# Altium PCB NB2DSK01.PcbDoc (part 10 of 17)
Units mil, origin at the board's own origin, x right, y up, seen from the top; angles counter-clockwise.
Board outline 11815 x 6500.03 mil, 8 copper layers (Top Layer, MidLayer1, MidLayer2, GND, PWR, MidLayer3, MidLayer4, Bottom Layer), stack 74.62 mil thick; 798 components, 1002 nets, 3927 pads, 3182 vias.
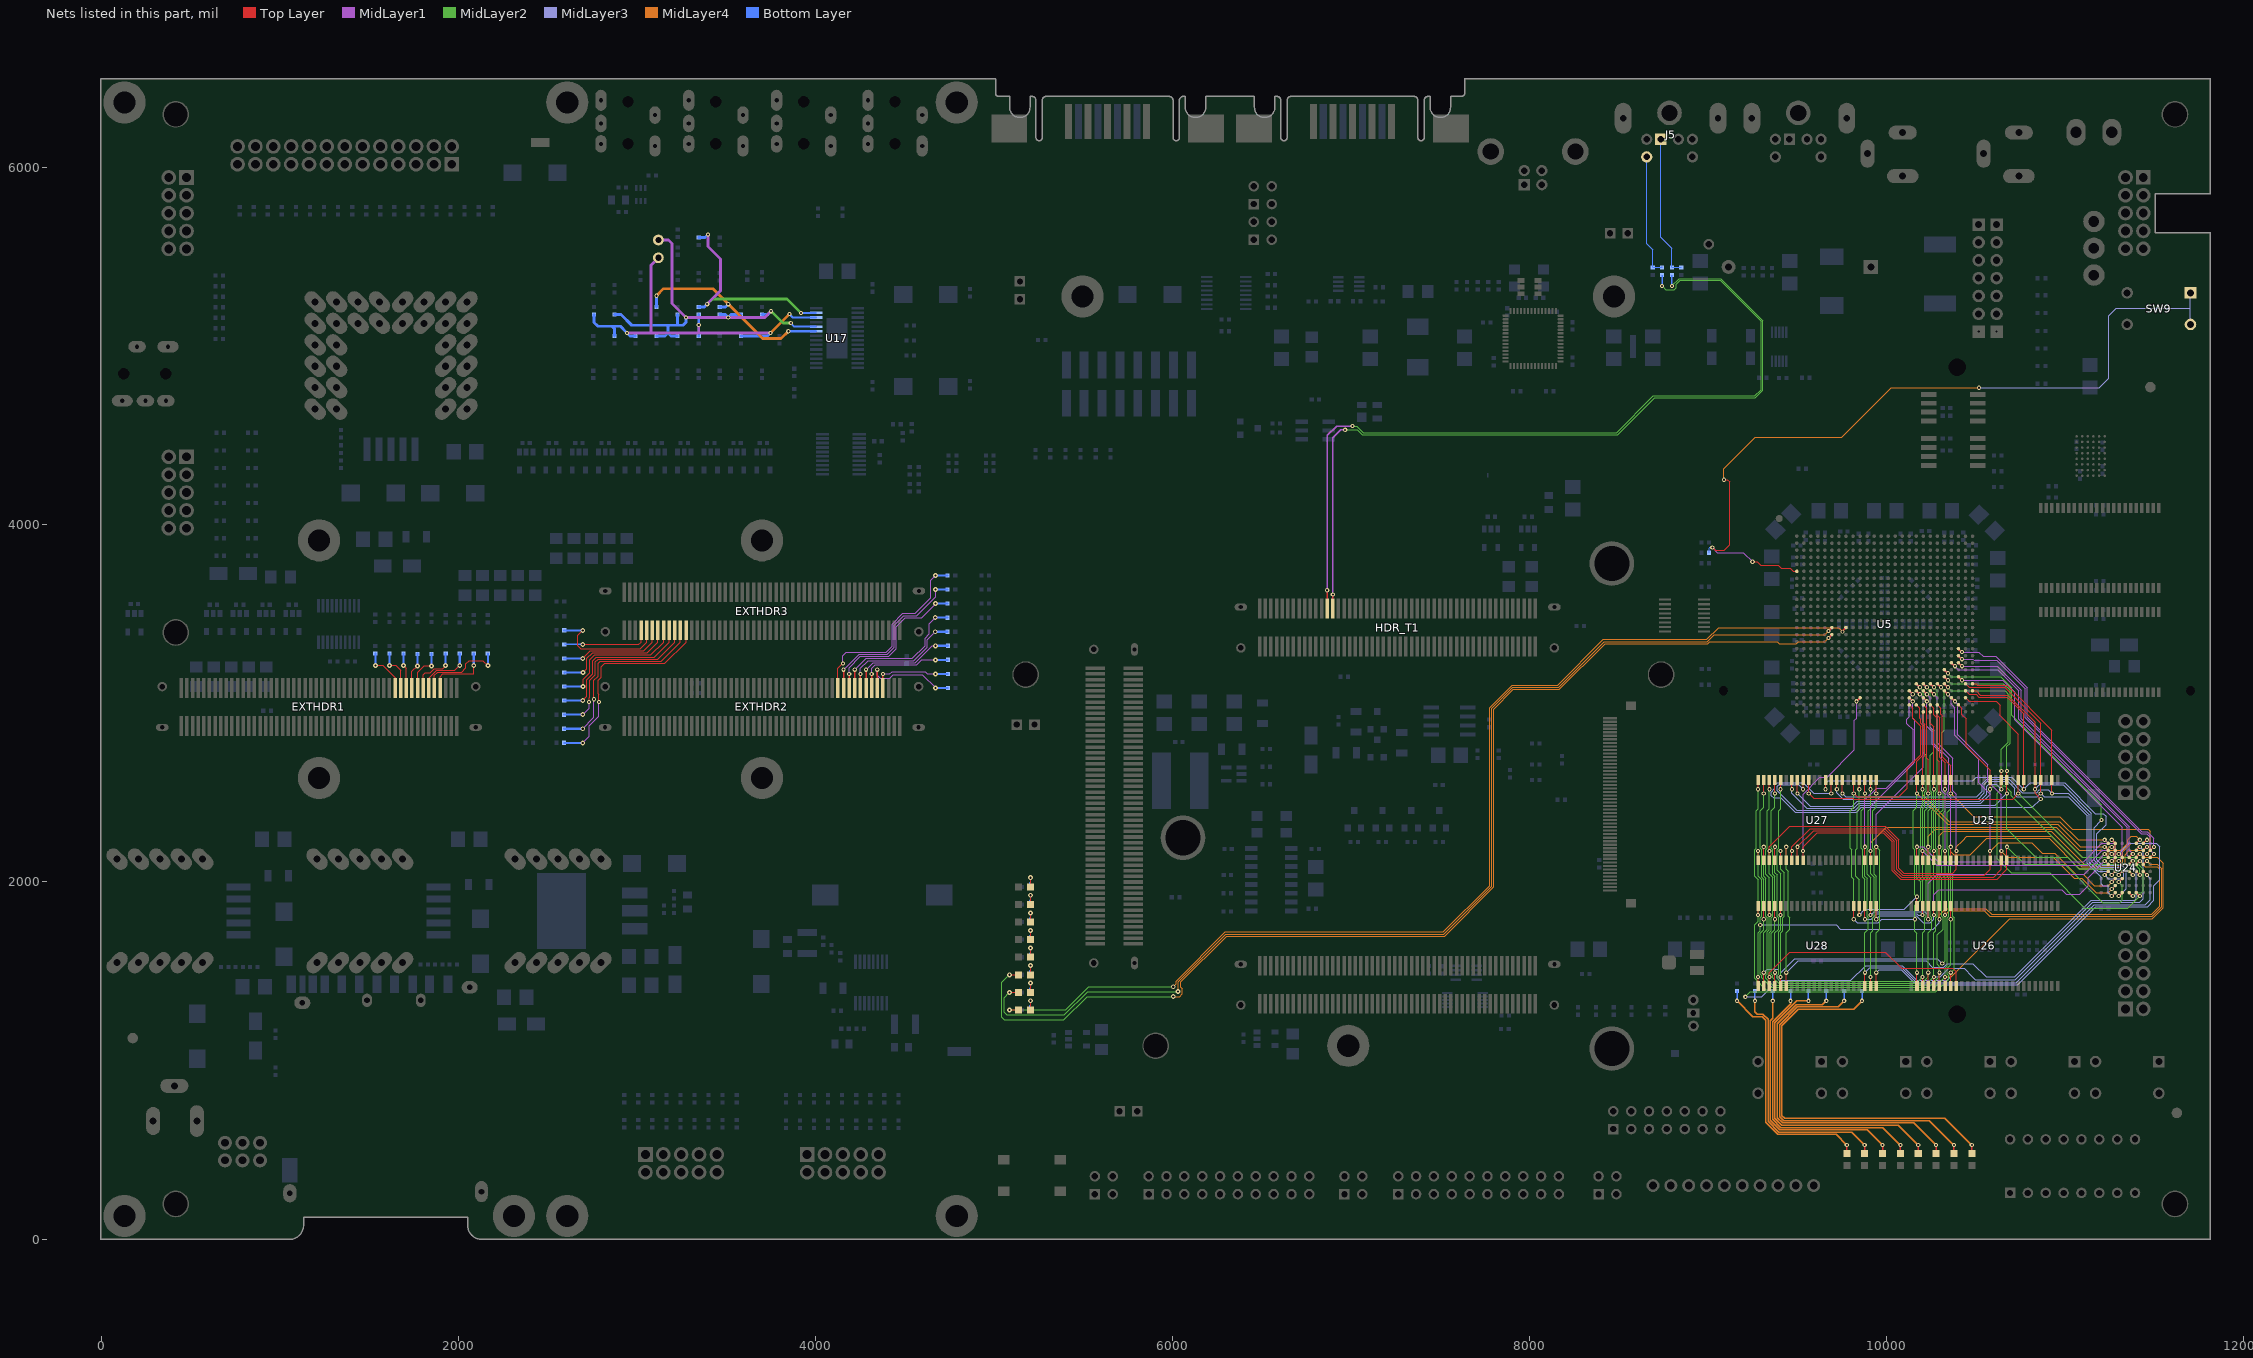
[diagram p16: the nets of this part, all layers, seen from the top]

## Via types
v1: diameter 23.62, hole 11.81, Top Layer to Bottom Layer, tented both sides, 1950 vias
v2: diameter 27.56, hole 11.81, Top Layer to Bottom Layer, tented both sides, 679 vias
v3: diameter 23.62, hole 11.81, Top Layer to Bottom Layer, 194 vias
v4: diameter 31.5, hole 11.81, Top Layer to Bottom Layer, tented both sides, 178 vias
v5: diameter 21.65, hole 11.81, Top Layer to Bottom Layer, tented both sides, 67 vias
v6: diameter 23.62, hole 11.81, Top Layer to Bottom Layer, tented bottom, 53 vias
v7: diameter 26, hole 11.81, Top Layer to Bottom Layer, tented both sides, 21 vias
v8: diameter 26, hole 11.81, Top Layer to Bottom Layer, 13 vias
v9: diameter 28, hole 11.81, Top Layer to Bottom Layer, 8 vias
v10: diameter 25.59, hole 11.81, Top Layer to Bottom Layer, tented both sides, 7 vias
v11: diameter 39.37, hole 11.81, Top Layer to Bottom Layer, tented both sides, 5 vias
v12: diameter 30, hole 11.81, Top Layer to Bottom Layer, 3 vias
v13: diameter 30, hole 11.81, Top Layer to Bottom Layer, tented both sides, 2 vias
v14: diameter 23, hole 11.81, Top Layer to Bottom Layer, tented both sides, 1 vias
v15: diameter 26.56, hole 11.81, Top Layer to Bottom Layer, tented both sides, 1 vias

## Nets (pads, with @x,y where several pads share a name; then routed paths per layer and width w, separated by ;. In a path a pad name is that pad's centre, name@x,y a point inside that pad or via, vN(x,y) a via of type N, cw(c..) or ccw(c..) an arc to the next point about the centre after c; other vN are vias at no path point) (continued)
HOST_LED.L5: LED6.1 U5.R6 | length 6500.6
  Top Layer w5: v2(5086.22,1480.32) LED6.1@5137.8,1480.32
  Top Layer w7.87: v1(9673.23,3366.14) U5.R6@9692.91,3385.83
  MidLayer2 w5: v2(5086.22,1480.32) 5043.59,1437.69 5043.59,1241.49 5057.38,1227.7 5391.93,1227.7 5522.5,1358.27 v2(6003.94,1358.27)
  MidLayer4 w5: v2(6003.94,1358.27) 6039.37,1358.27 6055.12,1374.02 6055.12,1401.58 6047.24,1409.45 6047.24,1440.95 6303.15,1696.85 7523.62,1696.85 7799.21,1972.44 7799.21,2968.5 7909.45,3078.74 8167.03,3078.74 8422.94,3334.65 8996.07,3334.65 9007.88,3346.46 9385.83,3346.46 9397.64,3334.65 9413.39,3334.65 9433.07,3334.65 9492.13,3334.65 9503.94,3346.46 9653.54,3346.46 v1(9673.23,3366.14)
HOST_LED.L6: LED7.1 U5.P6 | length 6342.4
  Top Layer w5: v2(5086.22,1381.89) LED7.1@5137.8,1381.89 ; v2@5090.55,1374.02 v2@5098.43,1381.89
  Top Layer w7.87: v1(9673.23,3405.51) U5.P6@9692.91,3425.2
  MidLayer2 w5: v2(5086.22,1381.89) 5057.38,1353.05 5057.38,1270.65 5072.75,1255.28 5393.51,1255.28 5524.05,1385.83 v2(6031.5,1385.83)
  MidLayer4 w5: v2(6031.5,1385.83) 6031.5,1440.95 6299.21,1708.66 7519.69,1708.66 7787.4,1976.38 7787.4,2972.44 7905.51,3090.55 8162.14,3090.55 8418.05,3346.46 8993.74,3346.46 9033.11,3385.83 9417.32,3385.83 9433.07,3385.83 9653.54,3385.83 v1(9673.23,3405.51)
HOST_LED.L7: LED8.1 U5.P8 | length 6234.9
  Top Layer w5: v2(5086.22,1283.47) LED8.1@5137.8,1283.47
  Top Layer w7.87: v5@9751.97,3405.51 U5.P8@9771.65,3425.2
  MidLayer2 w5: v2(5086.22,1283.47) 5400.69,1283.47 5530.61,1413.39 v2(6003.94,1413.39)
  MidLayer4 w5: v2(6003.94,1413.39) 6019.69,1429.13 6019.69,1444.88 6295.28,1720.47 7515.75,1720.47 7775.59,1980.32 7775.59,2976.38 7901.57,3102.36 8157.25,3102.36 8413.15,3358.27 8991.41,3358.27 9058.34,3425.2 9417.32,3425.2 9433.07,3425.2 9732.28,3425.2 v5@9751.97,3403.15
  other v5: 9751.97,3401.58
HOST_RESET_SW: R159.2 SW9.1 SW9.2 U5.F1 | length 4508.5
  Top Layer w5: v1(9023.23,3873.62) 9038.4,3858.45 9089.45,3858.45 9120,3889 9120,4241 9108,4253 v1(9088,4253) ; v2(9248.8,3793.33) 9274.66,3793.33 9294.54,3773.45 9391.68,3773.45 9409.23,3755.91 9460.63,3755.91 9476.38,3740.16 U5.F1@9496.06,3740.16
  MidLayer1 w5: v1(9023.23,3873.62) 9051.85,3845 9197.13,3845 v2(9248.8,3793.33)
  MidLayer4 w5: v1(9088,4253) 9088,4315 9264,4491 9749,4491 10026,4768 v1(10517,4768)
  MidLayer3 w5: v1(10517,4768) 11190,4768 11243,4821 11243,5171 11286,5214 11700.79,5214 ; SW9.2@11700.79,5122.51 SW9.1@11700.79,5299.67
  Bottom Layer w5: R159.2@9004.46,3843.38 9004.46,3869.06 9009.02,3873.62 v1(9023.23,3873.62)
IN.LEFT: R109.2 R112.2 R113.2 R114.2 R115.2 R116.1 TP13.1 U17.12 | length 2249.7
  MidLayer1 w15.75: v1(2944.88,5074.8) 3078.8,5074.8 ; TP13.1@3120.73,5495.67 3078.8,5453.74 3078.8,5074.8 ; 3346.46,5076.95 v1(3346.46,5119.64) ; v1(3748.03,5074.8) 3078.8,5074.8
  MidLayer4 w15.75: v1(3748.03,5074.8) v1(3854.33,5181.1)
  Bottom Layer w11.81: v1(3854.33,5181.1) 3874.02,5161.42 U17.12@4003.94,5161.42
  Bottom Layer w15.75: R115.2@2759.84,5177.64 2759.84,5133.95 2781.64,5112.15 2860.44,5112.15 ; R109.2@2874.02,5058.58 2874.02,5098.58 2860.44,5112.15 ; R112.2@2992.13,5058.58 2961.1,5058.58 v1(2944.88,5074.8) 2907.54,5112.15 2860.44,5112.15 ; R113.2@3346.46,5058.58 v1(3346.46,5119.64) R116.1@3346.46,5177.64 ; R114.2@3582.68,5058.58 3731.81,5058.58 v1(3748.03,5074.8)
IN.RIGHT: R119.2 R120.1 R121.2 R124.2 R125.2 R126.2 R129.2 TP14.1 U17.10 | length 2193.7
  MidLayer1 w15.75: TP14.1@3120.73,5595.67 3177.03,5595.67 3196.85,5575.85 3196.85,5240.16 v1(3275.59,5161.42) 3716.54,5161.42 v1(3751.97,5196.85)
  MidLayer2 w15.75: v1(3751.97,5196.85) 3818.9,5129.92 v1(3862.2,5129.92)
  Bottom Layer w11.81: v1(3862.2,5129.92) 3881.89,5110.24 U17.10@4003.94,5110.24
  Bottom Layer w15.75: R121.2@2874.02,5177.64 2911.46,5177.64 2970.99,5118.11 3259.22,5118.11 3275.59,5134.48 v1(3275.59,5161.42) ; R124.2@3110.24,5058.58 3157.45,5058.58 3174.06,5075.2 ; 3174.06,5118.11 3174.06,5075.2 ; R125.2@3228.35,5058.58 3190.68,5058.58 3174.06,5075.2 ; 3228.35,5119.6 R119.2@3228.35,5177.64 ; R120.1@3464.57,5177.64 3495.59,5177.64 v1(3511.81,5161.42) 3528.03,5177.64 R129.2@3582.68,5177.64 ; R126.2@3700.79,5177.64 3732.76,5177.64 v1(3751.97,5196.85)
JTAG.DETECTPBA: EXTHDR1.23 R207.2 | length 263.6
  Top Layer w5: v2(1535.43,3212.6) 1577.4,3212.6 1645.67,3144.33 EXTHDR1.23@1645.67,3086.61
  Bottom Layer w11.81: v2(1535.43,3212.6) R207.2@1535.43,3280
JTAG.DETECTPBB: EXTHDR2.23 R225.2 | length 1097.3
  Top Layer w5: EXTHDR2.23@4125.98,3086.61 4125.98,3196.85 v5(4153.54,3224.41)
  MidLayer1 w5: v5(4153.54,3224.41) 4153.54,3268.23 4172.72,3287.4 4397.64,3287.4 4429.13,3318.9 4429.13,3444.88 4488.19,3503.94 4559.06,3503.94 4645.67,3590.55 4645.67,3688.98 v2(4673.23,3716.54)
  Bottom Layer w11.81: v2(4673.23,3716.54) R225.2@4740.63,3716.54
JTAG.DETECTPBC: EXTHDR3.23 R243.2 | length 1176.8
  Top Layer w5: v1(2787.4,3007.87) 2787.4,3051.18 2783.46,3055.12 2783.46,3129.92 2799.21,3145.67 2799.21,3204.73 2818.9,3224.41 3157.48,3224.41 3275.59,3342.52 EXTHDR3.23@3275.59,3409.45
  MidLayer1 w5: v2(2696.85,2779.53) 2732.28,2814.96 2732.28,2874.02 2787.4,2929.13 v1(2787.4,3007.87)
  Bottom Layer w11.81: R243.2@2591.26,2779.53 v2(2696.85,2779.53)
JTAG.HARD.TCKPBA: EXTHDR1.11 R197.2 | length 324.2
  Top Layer w5: EXTHDR1.11@1834.65,3086.61 1834.65,3140.13 1879.87,3185.36 1980.63,3185.36 v2(2007.87,3212.6)
  Bottom Layer w11.81: v2(2007.87,3212.6) R197.2@2007.87,3280
JTAG.HARD.TCKPBB: EXTHDR2.11 R215.2 | length 557.4
  Top Layer w7.87: EXTHDR2.11@4314.96,3086.61 v1(4314.96,3165.36)
  MidLayer1 w5: v1(4314.96,3165.36) 4314.96,3196.85 4334.65,3216.54 4566.93,3216.54 4594.49,3244.1 v2(4673.23,3244.1)
  Bottom Layer w11.81: v2(4673.23,3244.1) R215.2@4742.6,3244.1
JTAG.HARD.TCKPBC: EXTHDR3.11 R233.2 | length 597.8
  Top Layer w5: v2(2696.85,3251.97) 2740.16,3295.28 3039.37,3295.28 3086.61,3342.52 EXTHDR3.11@3086.61,3409.45
  Bottom Layer w11.81: R233.2@2593.23,3251.97 v2(2696.85,3251.97)
JTAG.HARD.TDIPBA: EXTHDR1.7 R194.2 | length 372.4
  Top Layer w5: EXTHDR1.7@1897.64,3086.61 1897.64,3149.61 1913.39,3165.36 2085.36,3165.36 2086.61,3166.61 v2(2086.61,3212.6)
  Bottom Layer w11.81: v2(2086.61,3212.6) R194.2@2086.61,3280
JTAG.HARD.TDIPBB: EXTHDR2.7 R212.2 | length 453.2
  Top Layer w7.87: EXTHDR2.7@4377.95,3086.61 v1(4377.95,3165.36)
  MidLayer1 w5: v1(4377.95,3165.36) 4417.32,3165.36 4429.13,3177.17 4614.17,3177.17 4625.98,3165.36 v2(4673.23,3165.36)
  Bottom Layer w11.81: v2(4673.23,3165.36) R212.2@4742.6,3165.35
JTAG.HARD.TDIPBC: EXTHDR3.7 R230.2 | length 499
  Top Layer w5: v2(2696.85,3330.71) 3011.81,3330.71 3023.62,3342.52 EXTHDR3.7@3023.62,3409.45
  Bottom Layer w11.81: R230.2@2596.46,3333.47 v2(2696.85,3330.71)
JTAG.HARD.TDOPBA: EXTHDR1.9 R195.2 | length 496.1
  Top Layer w5: EXTHDR1.9@1866.14,3086.61 1866.14,3157.48 1884.02,3175.36 2018.36,3175.36 2043,3200 2043,3222.16 2061,3240.16 2137.8,3240.16 v2(2165.35,3212.6)
  Bottom Layer w11.81: v2(2165.35,3212.6) R195.2@2165.35,3280
JTAG.HARD.TDOPBB: EXTHDR2.9 R213.2 | length 575.7
  Top Layer w7.87: EXTHDR2.9@4346.46,3086.61 v1(4346.46,3188.98)
  MidLayer1 w5: v1(4346.46,3188.98) 4346.46,3157.48 4362.2,3141.73 4417.32,3141.73 4437.01,3161.42 4598.43,3161.42 v2(4673.23,3086.61)
  Bottom Layer w11.81: v2(4673.23,3086.61) R213.2@4742.6,3086.61
JTAG.HARD.TDOPBC: EXTHDR3.9 R231.2 | length 675.6
  Top Layer w5: v2(2696.85,3409.45) 2669.29,3381.89 2669.29,3322.84 2685.04,3307.09 3019.68,3307.09 3055.12,3342.52 EXTHDR3.9@3055.12,3409.45
  Bottom Layer w11.81: R231.2@2593.23,3409.45 v2(2696.85,3409.45)
JTAG.HARD.TMSPBA: EXTHDR1.13 R196.2 | length 289.2
  Top Layer w5: EXTHDR1.13@1803.15,3086.61 1803.15,3161.15 1815,3173 1842.85,3173 1865.21,3195.36 1911.89,3195.36 v2(1929.13,3212.6)
  Bottom Layer w11.81: v2(1929.13,3212.6) R196.2@1929.13,3280
JTAG.HARD.TMSPBB: EXTHDR2.13 R214.2 | length 616.9
  Top Layer w7.87: EXTHDR2.13@4283.47,3086.61 v1(4283.47,3188.98)
  MidLayer1 w5: v1(4283.47,3188.98) 4322.84,3228.35 4559.06,3228.35 4653.54,3322.84 v2(4673.23,3322.84)
  Bottom Layer w11.81: v2(4673.23,3322.84) R214.2@4742.6,3322.84
JTAG.HARD.TMSPBC: EXTHDR3.13 R232.2 | length 690.6
  Top Layer w5: v2(2698.82,3173.23) 2720.47,3194.88 2720.47,3251.97 2751.97,3283.47 3059.05,3283.47 3118.11,3342.52 EXTHDR3.13@3118.11,3409.45
  Bottom Layer w11.81: R232.2@2596.06,3171.65 v2@2696.85,3173.23
JTAG.SOFT.TCKPBA: EXTHDR1.19 R205.2 | length 199.9
  Top Layer w5: v2(1692.91,3212.6) 1708.66,3196.85 EXTHDR1.19@1708.66,3086.61
  Bottom Layer w11.81: v2(1692.91,3212.6) R205.2@1692.91,3280
JTAG.SOFT.TCKPBB: EXTHDR2.19 R223.2 | length 885.7
  Top Layer w7.87: EXTHDR2.19@4188.98,3086.61 v1(4188.98,3165.36)
  MidLayer1 w5: v1(4188.98,3165.36) 4188.98,3200.79 4251.97,3263.78 4409.45,3263.78 4452.76,3307.09 4452.76,3429.13 4503.94,3480.32 4594.49,3480.32 v2(4673.23,3559.06)
  Bottom Layer w11.81: v2(4673.23,3559.06) R223.2@4740.63,3559.06
JTAG.SOFT.TCKPBC: EXTHDR3.19 R241.2 | length 987.7
  Top Layer w5: v1(2732.28,3007.87) 2732.28,3031.5 2736.22,3035.43 2736.22,3129.92 2767.72,3161.42 2767.72,3232.28 2783.46,3248.03 3118.11,3248.03 3212.6,3342.52 EXTHDR3.19@3212.6,3409.45
  MidLayer1 w5: v2(2696.85,2937.01) 2732.28,2972.44 v1(2732.28,3007.87)
  Bottom Layer w11.81: R241.2@2591.26,2937.01 v2(2696.85,2937.01)
JTAG.SOFT.TDIPBA: EXTHDR1.15 R202.2 | length 248.5
  Top Layer w5: EXTHDR1.15@1771.65,3086.61 1771.65,3173.65 1808.63,3210.63 v2(1850.39,3210.63)
  Bottom Layer w11.81: v2(1850.39,3210.63) R202.2@1850.39,3278.03
JTAG.SOFT.TDIPBB: EXTHDR2.15 R220.2 | length 707.9
  Top Layer w7.87: EXTHDR2.15@4251.97,3086.61 v1(4251.97,3165.36)
  MidLayer1 w5: v1(4251.97,3165.36) 4251.97,3196.85 4295.28,3240.16 4551.18,3240.16 4625.98,3314.96 4625.98,3356.3 v2(4671.26,3401.58)
  Bottom Layer w11.81: v2(4671.26,3401.58) R220.2@4740.63,3401.58
JTAG.SOFT.TDIPBC: EXTHDR3.15 R238.2 | length 791.8
  Top Layer w5: v2(2698.82,3094.49) 2698.82,3135.83 2736.22,3173.23 2736.22,3244.1 2763.78,3271.65 3078.74,3271.65 3149.61,3342.52 EXTHDR3.15@3149.61,3409.45
  Bottom Layer w11.81: R238.2@2593.23,3094.49 v2(2698.82,3094.49)
JTAG.SOFT.TDOPBA: EXTHDR1.17 R203.2 | length 204.5
  Top Layer w5: EXTHDR1.17@1740.16,3086.61 1740.16,3179.13 v2(1771.65,3210.63)
  Bottom Layer w11.81: v2(1771.65,3210.63) R203.2@1771.65,3278.03
JTAG.SOFT.TDOPBB: EXTHDR2.17 R221.2 | length 802
  Top Layer w7.87: EXTHDR2.17@4220.47,3086.61 v1(4220.47,3188.98)
  MidLayer1 w5: v1(4220.47,3188.98) 4283.46,3251.97 4543.31,3251.97 4614.17,3322.84 4614.17,3366.14 4637.8,3389.76 4637.8,3446.85 v2(4671.26,3480.32)
  Bottom Layer w11.81: v2(4671.26,3480.32) R221.2@4740.63,3480.32
JTAG.SOFT.TDOPBC: EXTHDR3.17 R239.2 | length 891.3
  Top Layer w5: v2(2696.85,3015.75) 2720.47,3039.37 2720.47,3133.86 2751.97,3165.36 2751.97,3240.16 2771.65,3259.84 3098.42,3259.84 3181.1,3342.52 EXTHDR3.17@3181.1,3409.45
  Bottom Layer w11.81: R239.2@2593.23,3015.75 v2(2696.85,3015.75) v2@2698.82,3015.75
JTAG.SOFT.TMSPBA: EXTHDR1.21 R204.2 | length 240.7
  Top Layer w5: v2(1614.17,3212.6) 1650.4,3212.6 1677.17,3185.83 EXTHDR1.21@1677.17,3086.61
  Bottom Layer w11.81: v2(1614.17,3212.6) R204.2@1614.17,3280
JTAG.SOFT.TMSPBB: EXTHDR2.21 R222.2 | length 1021.6
  Top Layer w7.87: EXTHDR2.21@4157.48,3086.61 v1(4157.48,3188.98)
  MidLayer1 w5: v1(4157.48,3188.98) 4244.09,3275.59 4401.57,3275.59 4440.95,3314.96 4440.95,3437.01 4496.06,3492.13 4566.93,3492.13 4673.23,3598.43 v2(4673.23,3637.8)
  Bottom Layer w5: v2@4685.04,3637.8 R222.2@4740.63,3637.8
  Bottom Layer w11.81: v2(4673.23,3637.8) R222.2@4740.63,3637.8
JTAG.SOFT.TMSPBC: EXTHDR3.21 R240.2 | length 1084.1
  Top Layer w5: v1(2759.84,3023.62) 2759.84,3129.92 2783.46,3153.54 2783.46,3224.41 2795.28,3236.22 3137.79,3236.22 3244.09,3342.52 EXTHDR3.21@3244.09,3409.45
  MidLayer1 w5: v2(2696.85,2858.27) 2759.84,2921.26 v1(2759.84,3023.62)
  Bottom Layer w11.81: R240.2@2591.26,2858.27 v2(2696.85,2858.27)
KEYBOARD#.CLOCK: J5.5 R84.2 R87.2 | length 692.4
  Bottom Layer w5: J5.5@8655.51,6061.02 8655.51,5575.5 8689.73,5541.28 R84.2@8689.73,5441.69 R87.2@8741.35,5441.69
  Bottom Layer w7.87: R87.2@8736.22,5446.82 R87.2@8741.35,5441.69
KEYBOARD#.DATA: J5.1 R85.2 R86.2 | length 797.6
  Bottom Layer w5: J5.1@8736.51,6159.45 J5.1@8734.25,6159.45 8734.25,5610.9 8796.9,5548.25 R86.2@8796.9,5441.69 R85.2@8848.51,5441.69
KEYBOARD.CLOCK: HDR_T1.26 R87.1 | length 4671.4
  Top Layer w7.87: HDR_T1.26@6866.14,3531.5 v1(6866.14,3633.86)
  MidLayer1 w7.87: v1(6866.14,3633.86) 6866.14,4501.06 6918.54,4553.46 v1(7008.08,4553.46)
  MidLayer2 w5: v1(7008.08,4553.46) 7030.93,4553.46 7067.93,4516.45 8486.68,4516.45 8693.23,4723 9261.86,4723 9296,4757.14 9296,5140 9066.3,5369.7 8842.9,5369.7 8822.2,5349 8822.2,5329.2 8811.1,5318.1 8761.08,5318.1 v1(8741.35,5337.84)
  Bottom Layer w7.87: v1(8741.35,5337.84) R87.1@8741.35,5399.33
KEYBOARD.DATA: HDR_T1.28 R86.1 | length 4574.9
  Top Layer w7.87: HDR_T1.28@6897.64,3531.5 v1(6897.64,3610.24)
  MidLayer1 w7.87: v1(6897.64,3610.24) 6897.64,4487.66 6942.16,4532.18 v1(6966.71,4532.18)
  MidLayer2 w5: v1(6966.71,4532.18) 7033.69,4532.18 7062.42,4503.45 8493.68,4503.45 8701.23,4711 9264,4711 9306,4753 9306,5144.14 9070.44,5379.7 8838.76,5379.7 v1(8796.9,5337.84)
  Bottom Layer w7.87: v1(8796.9,5337.84) R86.1@8796.9,5399.33
LED#00: LED9.2 R100.2 | length 2244.7
  Top Layer w7.87: LED9.2@10476.38,479.41 v1(10476.38,526.65)
  MidLayer4 w8: v1(9861.4,1334.51) 9813.89,1287 9503.92,1287 9413,1196.08 9413,691.69 9427.69,677 10326.03,677 v1(10476.38,526.65)
  Bottom Layer w8: v1(9861.4,1334.51) R100.2@9861.4,1390.1
LED#0: LED1.2 R92.2 | length 105.3
  Top Layer w5: LED1.2@5204.73,1972.44 v2(5204.73,2024.02)
  Bottom Layer w5: R92.2@5199.53,1972.44 5199.53,1995.53 5204.73,2000.73 v2(5204.73,2024.02)
LED#1: LED2.2 R93.2 | length 105.3
  Top Layer w5: LED2.2@5204.73,1874.02 v2(5204.73,1925.59)
  Bottom Layer w5: R93.2@5199.53,1874.02 5199.53,1897.11 5204.73,1902.31 v2(5204.73,1925.59)
LED#01: LED10.2 R101.2 | length 2077
  Top Layer w7.87: LED10.2@10376.38,479.41 v1(10376.38,526.65)
  MidLayer4 w8: v1(9761.4,1334.51) 9726.89,1300 9498.54,1300 9400,1201.46 9400,686.31 9422.31,664 10239.03,664 v1(10376.38,526.65)
  Bottom Layer w8: v1(9761.4,1334.51) R101.2@9761.4,1390.1
LED#2: LED3.2 R94.2 | length 105.3
  Top Layer w5: LED3.2@5204.73,1775.59 v2(5204.73,1827.17)
  Bottom Layer w5: R94.2@5199.53,1775.59 5199.53,1798.68 5204.73,1803.88 v2(5204.73,1827.17)
LED#02: LED11.2 R102.2 | length 1909.3
  Top Layer w7.87: LED11.2@10276.38,479.41 v1(10276.38,526.65)
  MidLayer4 w8: v1(9661.4,1334.51) 9639.89,1313 9493.15,1313 9387,1206.85 9387,680.92 9416.92,651 10152.03,651 v1(10276.38,526.65)
  Bottom Layer w8: v1(9661.4,1334.51) R102.2@9661.4,1390.1
LED#3: LED4.2 R95.2 | length 105.3
  Top Layer w5: LED4.2@5204.73,1677.17 v2(5204.73,1728.74)
  Bottom Layer w5: R95.2@5199.53,1677.17 5199.53,1700.26 5204.73,1705.46 v2(5204.73,1728.74)
LED#03: LED12.2 R103.2 | length 1741.6
  Top Layer w7.87: LED12.2@10176.38,479.41 v1(10176.38,526.65)
  MidLayer4 w8: v1(9561.4,1334.51) 9496.28,1334.51 9374,1212.23 9374,675.54 9411.54,638 10065.03,638 v1(10176.38,526.65)
  Bottom Layer w8: v1(9561.4,1334.51) R103.2@9561.4,1390.1
LED#4: LED5.2 R96.2 | length 105.3
  Top Layer w5: LED5.2@5204.73,1578.74 v2(5204.73,1630.32)
  Bottom Layer w5: R96.2@5199.53,1578.74 5199.53,1601.83 5204.73,1607.03 v2(5204.73,1630.32)
LED#04: LED13.2 R104.2 | length 1583.6
  Top Layer w7.87: LED13.2@10076.38,479.41 v1(10076.38,526.65)
  MidLayer4 w8: v1(9461.4,1334.51) 9461.4,1318.01 9361,1217.62 9361,670.15 9406.15,625 9978.03,625 v1(10076.38,526.65)
  Bottom Layer w8: v1(9461.4,1334.51) R104.2@9461.4,1390.1
LED#5: LED6.2 R97.2 | length 105.3
  Top Layer w5: LED6.2@5204.73,1480.32 v2(5204.73,1531.89)
  Bottom Layer w5: R97.2@5199.53,1480.32 5199.53,1503.41 5204.73,1508.61 v2(5204.73,1531.89)
LED#05: LED14.2 R105.2 | length 1463.7
  Top Layer w7.87: LED14.2@9976.38,479.41 v1(9976.38,526.65)
  MidLayer4 w8: v1(9361.4,1334.51) 9361.4,1236.4 9348,1223 9348,664.77 9400.77,612 9891.03,612 v1(9976.38,526.65)
  Bottom Layer w8: v1(9361.4,1334.51) R105.2@9361.4,1390.1
LED#6: LED7.2 R98.2 | length 105.3
  Top Layer w5: LED7.2@5204.73,1381.89 v2(5204.73,1433.47)
  Bottom Layer w5: R98.2@5199.53,1381.89 5199.53,1404.98 5204.73,1410.18 v2(5204.73,1433.47)
LED#06: LED15.2 R106.2 | length 1424.1
  Top Layer w7.87: LED15.2@9876.38,479.41 v1(9876.38,526.65)
  MidLayer4 w8: v1(9261.4,1334.51) 9261.4,1272 9273.4,1260 9306.38,1260 9335,1231.38 9335,659.38 9395.38,599 9804.03,599 v1(9876.38,526.65)
  Bottom Layer w8: v1(9261.4,1334.51) R106.2@9261.4,1390.1
LED#7: LED8.2 R99.2 | length 105.3
  Top Layer w5: LED8.2@5204.73,1283.47 v2(5204.73,1335.04)
  Bottom Layer w5: R99.2@5199.53,1283.47 5199.53,1306.56 5204.73,1311.76 v2(5204.73,1335.04)
LED#07: LED16.2 R107.2 | length 1387.5
  Top Layer w7.87: LED16.2@9776.38,479.41 v1(9776.38,526.65)
  MidLayer4 w8: v1(9161.4,1334.51) 9249.91,1246 9302,1246 9322,1226 9322,654 9390,586 9717.03,586 v1(9776.38,526.65)
  Bottom Layer w8: v1(9161.4,1334.51) R107.2@9161.4,1390.1
LINEAOUT_L: R116.2 R130.1 U17.13 | length 1221
  MidLayer1 w15.75: v1(3393.7,5236.22) 3468.5,5311.02 3468.5,5488.19 3397.64,5559.06 v1(3397.64,5625.98) ; v1@3397.64,5236.22 v1@3397.64,5240.16
  MidLayer2 w15.75: v1(3393.7,5236.22) 3423.23,5265.75 3840.55,5265.75 v1(3919.29,5187.01)
  Bottom Layer w11.81: v1(3919.29,5187.01) U17.13@4003.94,5187.01
  Bottom Layer w15.75: R116.2@3346.46,5220 3377.48,5220 v1(3393.7,5236.22) ; R130.1@3346.46,5609.76 3381.42,5609.76 v1(3397.64,5625.98)
LINEAOUT_R: R120.2 R127.1 U17.9 | length 1160.3
  MidLayer4 w15.75: v1(3110.24,5283.47) 3149.61,5322.84 3425.2,5322.84 v1(3511.81,5236.22) 3704.72,5043.31 3807.09,5043.31 v1(3848.43,5084.65)
  Bottom Layer w11.81: v1(3848.43,5084.65) U17.9@4003.94,5084.65
  Bottom Layer w15.75: R127.1@3110.24,5220 v1(3110.24,5283.47) ; R120.2@3464.57,5220 3495.59,5220 v1(3511.81,5236.22)
MEM.BUS_A1: U5.Y22 U24.E2 | length 1986
  Top Layer w5: v1(11220.47,2039.19) U24.E2@11240.16,2058.88
  Top Layer w7.87: U5.Y22@10322.83,3188.98 v1(10342.52,3169.29)
  MidLayer2 w5: v1(10342.52,3169.29) 10362.21,3149.61 10543.31,3149.61 10566.93,3149.61 10637.8,3149.61 10700.79,3086.61 10700.79,2933.07 10984.25,2649.61 11202.5,2431.36 v1(11202.5,2346.7)
  MidLayer3 w5: v1(11202.5,2346.7) 11160.68,2304.88 11160.68,2121.95 11198.68,2083.95 11308.59,2083.95 11327.76,2064.78 11327.76,2025.41 11321.85,2019.51 11240.16,2019.51 v1(11220.47,2039.19)
MEM.BUS_A2: U5.AF20 U24.D2 U25.23 U26.23 U27.1 U28.1 | length 3687.8
  Top Layer w5: v1(9940.94,1791.34) U28.1@9940.95,1866.14 ; v1(9940.94,2496.06) U27.1@9940.95,2570.87 ; U5.AF20@10244.09,2952.76 10244.09,2889.76 10263.78,2870.08 U25.23@10263.78,2570.87 v1(10263.78,2519.69) ; v1(10263.78,1814.96) U26.23@10263.78,1866.14 ; v1(11220.47,2117.93) U24.D2@11240.16,2098.25
  MidLayer1 w5: v1(10263.78,1814.96) 10263.78,1929.5 10290.97,1956.69 10979.6,1956.69 11004.69,1931.6 11079.8,1931.6 11127.6,1979.4 11127.6,2025.06 v1(11220.47,2117.93)
  MidLayer2 w5: v1(9940.94,1791.34) 9940.94,2031.5 9929.13,2043.31 9929.13,2181.1 9921.26,2188.98 9921.26,2397.64 9940.94,2417.32 v1(9940.94,2496.06) ; v1(10263.78,1814.96) 10263.78,2015.75 10244.1,2035.43 10244.1,2181.1 10251.97,2188.98 10251.97,2397.64 10263.78,2409.45 v1(10263.78,2519.69)
  MidLayer3 w5: v1(9940.94,1791.34) 9960.63,1811.02 10165.35,1811.02 10204.72,1771.65 10244.09,1771.65 10263.78,1791.34 v1(10263.78,1814.96)
MEM.BUS_A3: U5.AE19 U24.C2 U25.24 U26.24 U27.2 U28.2 | length 3775
  Top Layer w5: v1(9909.45,1814.96) U28.2@9909.45,1866.14 ; v1(9909.45,2519.69) U27.2@9909.45,2570.87 ; U5.AE19@10204.72,2992.13 10224.41,2972.44 10224.41,2693.44 10232.28,2685.56 U25.24@10232.28,2570.87 v1(10232.28,2496.06) ; v1(10232.28,1791.34) U26.24@10232.28,1866.14 ; v1(11220.47,2157.3) U24.C2@11240.16,2137.62
  MidLayer1 w5: v1(10232.28,1791.34) 10232.28,1992.56 10283.03,2043.31 11106.48,2043.31 11188.98,2125.81 v1(11220.47,2157.3)
  MidLayer2 w5: v1(9909.45,1814.96) 9909.45,2023.62 9889.76,2043.31 9889.76,2181.1 9897.64,2188.98 9897.64,2397.64 9909.45,2409.45 v1(9909.45,2519.69) ; v1(10232.28,1791.34) 10232.28,2011.81 10220.47,2023.62 10220.47,2181.1 10212.6,2188.98 10212.6,2397.64 10232.28,2417.32 v1(10232.28,2496.06)
  MidLayer3 w5: v1(9909.45,1814.96) 9929.13,1834.65 10212.6,1834.65 10232.28,1814.96 v1(10232.28,1791.34)
MEM.BUS_A4: U5.AF19 U24.A2 U25.25 U26.25 U27.3 U28.3 | length 3606.7
  Top Layer w5: v1(9877.95,1791.34) U28.3@9877.95,1866.14 ; v1(9877.95,2496.06) U27.3@9877.95,2570.87 ; v1(10200.79,1814.96) U26.25@10200.79,1866.14 ; v1(10200.79,2519.69) U25.25@10200.79,2570.87 10200.79,2694.5 10212.68,2706.4 10212.68,2884.54 10204.72,2892.5 U5.AF19@10204.72,2952.76 ; v1(11220.47,2236.04) U24.A2@11240.16,2216.36
  MidLayer2 w5: v1(9877.95,1791.34) 9877.95,2015.75 9866.14,2027.56 9866.14,2181.1 9858.27,2188.98 9858.27,2397.64 9877.95,2417.32 v1(9877.95,2496.06) ; v1(10200.79,1814.96) 10200.79,2007.87 10181.1,2027.56 10181.1,2181.1 10188.98,2188.98 10188.98,2417.32 10200.79,2429.14 v1(10200.79,2519.69)
  MidLayer4 w5: v1(10200.79,2519.69) 10200.79,2488.19 10350.39,2338.58 10968.5,2338.58 11071.04,2236.04 v1(11220.47,2236.04)
  MidLayer3 w5: v1(9877.95,1791.34) 9913.39,1791.34 9944.88,1822.83 10169.29,1822.83 10177.17,1814.96 v1(10200.79,1814.96)
MEM.BUS_A5: U5.AE18 U24.B2 U25.26 U26.26 U27.4 U28.4 | length 3563.2
  Top Layer w5: v1(9846.46,1814.96) U28.4@9846.46,1866.14 ; v1(9846.46,2519.69) U27.4@9846.46,2570.87 ; U5.AE18@10165.35,2992.13 10185.04,2972.44 10185.04,2916.44 10190.83,2910.65 10190.83,2889.66 10202.68,2877.81 10202.68,2710.54 10169.29,2677.15 U25.26@10169.29,2570.87 v1(10169.29,2496.06) ; U26.26@10169.29,1866.14 v1(10169.29,1917.32) ; v1(11220.47,2196.67) U24.B2@11240.16,2176.99
  MidLayer2 w5: v1(9846.46,1814.96) 9846.46,2011.81 9826.77,2031.5 9826.77,2181.1 9834.65,2188.98 9834.65,2397.64 9846.46,2409.45 v1(9846.46,2519.69) ; v1(10169.29,1917.32) 10157.48,1929.13 10157.48,2181.1 10149.61,2188.98 10149.61,2397.64 10169.29,2417.32 v1(10169.29,2496.06)
  MidLayer4 w5: v1(10169.29,2496.06) 10342.52,2322.84 10956.69,2322.84 11082.86,2196.67 v1(11220.47,2196.67)
  MidLayer3 w5: v1(9846.46,1814.96) 9877.95,1846.46 10098.43,1846.46 v1(10169.29,1917.32)
MEM.BUS_A6: U5.AE17 U24.D3 U25.29 U26.29 U27.5 U28.5 | length 4281.3
  Top Layer w5: v1(9814.96,1791.34) U28.5@9814.96,1866.14 ; U27.5@9814.96,2570.87 v1(9814.96,2496.06) 9834.64,2476.38 10066.93,2476.38 10114.17,2523.62 10114.17,2636.17 10191.68,2713.68 10191.68,2871.31 10145.67,2917.32 10145.67,2972.44 U5.AE17@10125.98,2992.13 ; U26.29@10169.29,1417.32 v1(10169.29,1492.13) ; U25.29@10169.29,2122.05 v1(10169.29,2196.85) ; v1(11259.84,2117.93) U24.D3@11279.53,2098.25
  MidLayer1 w5: v1(10169.29,2196.85) 10204.72,2196.85 10287.4,2114.17 11102.54,2114.17 11204.72,2216.36 11271.65,2216.36 11279.53,2208.49 11279.53,2137.62 v1(11259.84,2117.93)
  MidLayer2 w5: v1(9814.96,1791.34) 9814.96,2015.75 9803.15,2027.56 9803.15,2181.1 9795.28,2188.98 9795.28,2397.64 9814.96,2417.32 v1(9814.96,2496.06) ; v1(10169.29,1492.13) 10169.29,1712.6 10157.48,1724.41 10157.48,1870.08 10188.98,1901.58 10188.98,2000 10169.29,2019.69 v1(10169.29,2196.85)
  MidLayer3 w5: v1(9814.96,1791.34) 9834.65,1771.65 9952.76,1771.65 9972.44,1791.34 v1(10157.48,1791.34)
MEM.BUS_A7: U5.AB18 U24.C3 U25.30 U26.30 U27.18 U28.18 | length 4970.4
  Top Layer w5: v1(9405.51,1814.96) U28.18@9405.51,1866.14 ; v1(9405.51,2519.69) U27.18@9405.51,2570.87 ; U26.30@10200.79,1417.32 v1(10200.79,1468.5) ; U25.30@10200.79,2122.05 v1(10200.79,2173.23) ; v1(11259.84,2157.3) U24.C3@11279.53,2137.62
  Top Layer w7.87: U5.AB18@10165.35,3110.24 v1(10185.04,3090.55)
  MidLayer1 w5: v1(10200.79,2173.23) 10279.56,2094.45 11125.3,2094.45 11207.8,2176.95 11240.19,2176.95 v1(11259.84,2157.3)
  MidLayer2 w5: v1(9405.51,2519.69) 9405.51,2409.45 9393.7,2397.64 9393.7,2188.98 9385.83,2181.1 9385.83,2066.93 9405.51,2047.24 9405.51,1732.28 9393.7,1720.47 9393.7,1484.25 9385.83,1476.38 9385.83,1460.63 9401.57,1444.88 10177.17,1444.88 v1(10200.79,1468.5) 10200.79,1716.54 10212.6,1728.35 10212.6,1799.21 10220.47,1807.09 10220.47,2007.87 10200.79,2027.56 10200.79,2409.45 10212.6,2421.26 10212.6,2503.94 10220.47,2511.81 10220.47,2708.66 10204.72,2724.41 10204.72,2870.08 10204.72,2889.76 10204.72,3070.87 v1(10185.04,3090.55)
MEM.BUS_A8: U5.AB19 U24.A3 U25.31 U26.31 U27.19 U28.19 | length 5266.8
  Top Layer w5: v1(9374.02,1791.34) U28.19@9374.02,1866.14 ; v1(9374.02,2496.06) U27.19@9374.02,2570.87 ; U26.31@10232.28,1417.32 v1(10232.28,1492.13) ; U25.31@10232.28,2122.05 v1(10232.28,2196.85) ; v1(11259.84,2236.04) U24.A3@11279.53,2216.36
  Top Layer w7.87: U5.AB19@10204.72,3110.24 v1(10224.41,3090.55)
  MidLayer2 w5: v1(9374.02,2496.06) 9374.02,2417.32 9354.33,2397.64 9354.33,2188.98 9362.21,2181.1 9362.21,2043.31 9374.02,2031.5 9374.02,1732.28 9354.33,1712.6 9354.33,1484.25 9362.2,1476.38 9362.2,1464.57 9393.7,1433.07 10196.85,1433.07 10232.28,1468.51 10232.28,1716.54 10251.97,1736.22 10251.97,1799.21 10244.1,1807.09 10244.1,2015.75 10232.28,2027.56 10232.28,2397.64 10251.97,2417.32 10251.97,2503.94 10244.09,2511.81 10244.09,2708.66 10263.78,2728.35 10263.78,2842.52 10244.09,2862.21 10244.09,2870.08 10244.09,2889.76 10244.09,3070.87 v1(10224.41,3090.55)
  MidLayer4 w5: v1(10232.28,2196.85) 10232.28,2255.91 10271.65,2295.28 10937.01,2295.28 11094.67,2137.62 11232.28,2137.62 11240.16,2145.49 11240.16,2169.11 11248.03,2176.99 11271.65,2176.99 11279.53,2184.86 11279.53,2216.36 v1(11259.84,2236.04)
MEM.BUS_A9: U5.AB20 U24.B6 U25.32 U26.32 U27.20 U28.20 | length 5681
  Top Layer w5: v1(9342.52,1814.96) U28.20@9342.52,1866.14 ; v1(9342.52,2519.69) U27.20@9342.52,2570.87 ; U26.32@10263.78,1417.32 v1(10263.78,1468.5) ; U25.32@10263.78,2122.05 v1(10263.78,2173.23) ; U24.B6@11397.64,2176.99 v1(11417.32,2196.67)
  Top Layer w7.87: U5.AB20@10244.09,3110.24 v1(10263.78,3090.55)
  MidLayer2 w5: v1(9342.52,2519.69) 9342.52,2409.45 9330.71,2397.64 9330.71,2188.98 9322.84,2181.1 9322.84,2043.31 9342.52,2023.62 9342.52,1732.28 9330.71,1720.47 9330.71,1484.25 9322.83,1476.38 9322.83,1460.63 9362.2,1421.26 10216.54,1421.26 v1(10263.78,1468.5) 10263.78,1716.54 10275.59,1728.35 10275.59,1799.21 10283.47,1807.09 10283.47,2015.75 10263.78,2035.43 10263.78,2393.7 10275.59,2405.51 10275.59,2503.94 10283.46,2511.81 10283.46,2870.08 10283.46,2889.76 10283.46,3070.87 v1(10263.78,3090.55)
  MidLayer3 w5: v1(10263.78,1468.5) 10299.21,1468.5 10346.46,1515.75 10433.07,1515.75 10476.38,1472.44 10495.82,1453 10720.89,1453 11153.54,1885.65 11417.32,1885.65 11437.01,1905.34 11437.01,2176.99 v1(11417.32,2196.67)
MEM.BUS_A10: U5.AB21 U24.A6 U25.33 U26.33 U27.21 U28.21 | length 5522.7
  Top Layer w5: v1(9311.02,1791.34) U28.21@9311.02,1866.14 ; v1(9311.02,2496.06) U27.21@9311.02,2570.87 ; U26.33@10295.28,1417.32 v1(10295.28,1492.13) ; U25.33@10295.28,2122.05 v1(10295.28,2196.85) ; U24.A6@11397.64,2216.36 v1(11417.32,2236.04)
  Top Layer w7.87: U5.AB21@10283.46,3110.24 v1(10303.15,3090.55)
  MidLayer2 w5: v1(9311.02,2496.06) 9311.02,2417.32 9291.34,2397.64 9291.34,2188.98 9299.21,2181.1 9299.21,2027.56 9311.02,2015.75 9311.02,1732.28 9291.34,1712.6 9291.34,1484.25 9299.21,1476.38 9299.21,1464.57 9354.33,1409.45 10236.22,1409.45 10295.28,1468.51 10295.28,1527.56 10283.46,1539.37 10283.46,1704.72 10314.96,1736.22 10314.96,1799.21 10307.09,1807.09 10307.09,2023.62 10295.28,2035.43 10295.28,2078.74 10295.28,2385.83 10314.96,2405.51 10314.96,2503.94 10307.09,2511.81 10307.09,2834.65 10322.83,2850.39 10322.83,2874.02 10322.83,2889.76 10322.83,3070.87 v1(10303.15,3090.55)
  MidLayer4 w5: v1(10295.28,2196.85) 10295.28,2259.84 10318.9,2283.47 10921.26,2283.47 11106.48,2098.25 11271.65,2098.25 11279.53,2106.12 11279.53,2165.18 11291.34,2176.99 11311.02,2176.99 11350.39,2216.36 11350.39,2236.04 11370.08,2255.73 11397.64,2255.73 v1(11417.32,2236.04)
MEM.BUS_A11: U5.AD19 U24.C6 U25.34 U26.34 U27.22 U28.22 | length 5853.5
  Top Layer w5: v1(9279.53,1814.96) U28.22@9279.53,1866.14 ; v1(9279.53,2519.69) U27.22@9279.53,2570.87 ; U26.34@10326.77,1417.32 v1(10326.77,1468.5) ; U25.34@10326.77,2122.05 v1(10326.77,2173.23) ; U24.C6@11397.64,2137.62 v1(11417.32,2157.3)
  Top Layer w7.87: U5.AD19@10204.72,3031.5 v1(10224.41,3011.81)
  MidLayer1 w5: v1(10224.41,3011.81) 10224.41,2889.77 10224.41,2874.02 10224.41,2871.69 10253.78,2842.32 10253.78,2771.45 10307.09,2718.14 10307.09,2511.81 10326.77,2492.13 v1(10326.77,2173.23)
  MidLayer2 w5: v1(9279.53,2519.69) 9279.53,2409.45 9267.72,2397.64 9267.72,2188.98 9259.84,2181.1 9259.84,2031.5 9279.53,2011.81 9279.53,1779.53 9259.84,1759.84 9259.84,1460.63 9322.83,1397.64 10255.91,1397.64 v1(10326.77,1468.5) 10326.77,1519.69 10338.58,1531.5 10338.58,1799.21 10346.46,1807.09 10346.46,2023.62 10326.77,2043.31 v1(10326.77,2173.23)
  MidLayer4 w5: v1(10326.77,1468.5) 10362.2,1468.5 10688.98,1795.28 11488.19,1795.28 11549.68,1856.77 11549.68,2103.69 11515.75,2137.62 11437.01,2137.62 v1(11417.32,2157.3)
MEM.BUS_A12: U5.AE20 U24.D6 U25.22 U26.22 U27.23 U28.23 | length 4854.9
  Top Layer w5: U28.23@9279.53,1417.32 v1(9279.53,1468.5) ; U27.23@9279.53,2122.05 v1(9279.53,2173.23) ; U5.AE20@10244.09,2992.13 10263.78,2972.44 10263.78,2937.01 10283.46,2917.32 10283.46,2684.67 10295.28,2672.86 U25.22@10295.28,2570.87 v1(10295.28,2496.06) ; v1(10295.28,1791.34) U26.22@10295.28,1866.14 ; U24.D6@11397.64,2098.25 v1(11417.32,2117.93)
  MidLayer2 w5: v1(9279.53,1468.5) 9279.53,1716.54 9291.34,1728.35 9291.34,1799.21 9299.21,1807.09 9299.21,2011.81 9279.53,2031.5 v1(9279.53,2173.23) ; v1(10295.28,1791.34) 10295.28,2019.69 10283.47,2031.5 10283.47,2181.1 10275.59,2188.98 10275.59,2370.08 10275.59,2389.76 10295.28,2409.45 v1(10295.28,2496.06)
  MidLayer4 w5: v1(10295.28,1791.34) 10295.28,1814.96 10330.71,1850.39 10555.17,1850.39 10586.67,1818.9 11483.53,1818.9 11529.68,1865.05 11529.68,2070.76 11514,2086.44 11448.82,2086.44 v1(11417.32,2117.93)
  MidLayer3 w5: v1(9291.34,1759.84) 9716.54,1759.84 9740.16,1736.22 10259.84,1736.22 10295.28,1771.65 v1(10295.28,1791.34)
MEM.BUS_A13: U5.AC19 U24.B7 U25.35 U26.35 U27.24 U28.24 | length 5249.9
  Top Layer w5: U28.24@9311.02,1417.32 v1(9311.02,1492.13) ; U27.24@9311.02,2122.05 v1(9311.02,2196.85) ; U26.35@10358.27,1417.32 v1(10358.27,1492.13) ; U25.35@10358.27,2122.05 v1(10358.27,2196.85) ; U24.B7@11437.01,2176.99 v1@11456.69,2196.67
  Top Layer w7.87: U5.AC19@10204.72,3070.87 v1(10224.41,3051.18)
  MidLayer1 w5: v1(10224.41,3051.18) 10244.09,3031.5 10244.09,2889.76 10244.09,2874.02 10244.09,2866.14 10263.78,2846.46 10263.78,2775.59 10346.46,2692.91 10346.46,2511.81 10338.58,2503.94 10338.58,2488.19 10358.27,2468.5 v1(10358.27,2196.85)
  MidLayer2 w5: v1(9311.02,1492.13) 9311.02,1716.54 9330.71,1736.22 9330.71,1799.21 9322.83,1807.09 9322.83,2019.68 9311.02,2031.5 v1(9311.02,2196.85) ; v1(10358.27,1492.13) 10377.95,1511.81 10377.95,1799.21 10370.08,1807.09 10370.08,2031.49 10358.27,2043.31 v1(10358.27,2196.85)
  MidLayer4 w5: v1(10358.27,2196.85) 10358.27,2169.29 10374.02,2153.54 10468.5,2153.54 10559.06,2244.09 10909.45,2244.09 11078.92,2074.63 11299.21,2074.63 11334.65,2110.06 11334.65,2153.37 11358.27,2176.99 11437.01,2176.99 v1(11456.69,2196.67)
  MidLayer3 w5: v1(9311.02,1492.13) 9330.71,1511.81 9389.76,1511.81 9393.7,1507.87 9393.7,1484.25 9385.83,1476.38 9385.83,1460.63 9397.64,1448.82 9799.21,1448.82 9881.89,1531.5 10086.61,1531.5 10169.29,1448.82 10338.58,1448.82 10358.27,1468.5 v1(10358.27,1492.13)
MEM.BUS_A14: U5.AC20 U24.A7 U25.36 U26.36 U27.25 U28.25 | length 5761.5
  Top Layer w5: U28.25@9342.52,1417.32 v1(9342.52,1468.5) 9342.52,1492.13 9456.69,1606.3 9992.13,1606.3 10082.68,1515.75 10370.08,1515.75 10389.76,1496.06 U26.36@10389.76,1417.32 ; U27.25@9342.52,2122.05 v1(9342.52,2173.23) 9342.52,2196.85 9456.69,2311.02 9992.13,2311.02 10066.93,2236.22 10066.93,2078.2 10095.68,2049.45 10368.35,2049.45 10389.76,2070.87 U25.36@10389.76,2122.05 v1(10389.76,2173.23) ; U24.A7@11437.01,2216.36 v1(11456.69,2236.04)
  Top Layer w7.87: U5.AC20@10244.09,3070.87 v1(10263.78,3051.18)
  MidLayer1 w5: v1(10263.78,3051.18) 10283.46,3031.5 10283.46,2889.76 10283.46,2874.02 10283.46,2779.53 10370.08,2692.91 10370.08,2511.81 10389.76,2492.13 v1(10389.76,2173.23)
  MidLayer2 w5: v1(9342.52,1468.5) 9342.52,1716.54 9354.33,1728.35 9354.33,1799.21 9362.2,1807.09 9362.2,2027.56 9342.52,2047.24 v1(9342.52,2173.23)
  MidLayer4 w5: v1(10389.76,2173.23) 10389.76,2196.85 10424.88,2231.96 10448.82,2255.91 10921.26,2255.91 11090.73,2086.44 11295.28,2086.44 11322.83,2114 11322.83,2169.11 11370.08,2216.36 11437.01,2216.36 v1(11456.69,2236.04)
MEM.BUS_A15: U5.AE21 U24.C7 U25.20 U26.20 U27.26 U28.26 | length 5344.8
  Top Layer w5: U28.26@9374.02,1417.32 v1(9374.02,1492.13) ; U27.26@9374.02,2122.05 v1(9374.02,2196.85) ; U5.AE21@10283.46,2992.13 10303.39,2972.21 10303.39,2938.75 10309.68,2932.45 10309.68,2700.45 10358.27,2651.87 U25.20@10358.27,2570.87 v1(10358.27,2496.06) ; v1(10358.27,1791.34) U26.20@10358.27,1866.14 ; U24.C7@11437.01,2137.62 v1(11456.69,2157.3)
  MidLayer2 w5: v1(9208,1357) 9236.83,1385.83 10275.59,1385.83 10346.46,1456.69 10346.46,1476.38 10338.58,1484.25 10338.58,1515.75 10358.27,1535.43 10358.27,2027.56 ; v1(9374.02,1492.13) 9374.02,1716.54 9393.7,1736.22 9393.7,1751.97 9393.7,1799.21 9385.83,1807.09 9385.83,2039.37 9374.02,2051.18 v1(9374.02,2196.85) ; 10358.27,2027.56 10346.46,2039.37 10346.46,2181.1 10338.58,2188.98 10338.58,2377.95 10338.58,2389.76 10358.27,2409.45 v1(10358.27,2496.06)
  MidLayer4 w5: v1(10358.27,2496.06) 10488.19,2366.14 10968.5,2366.14 11039.55,2295.1 11464.57,2295.1 11476.38,2283.29 11476.38,2176.99 v1(11456.69,2157.3)
  MidLayer3 w5: v1(9208,1357) 9299,1357 9374.02,1432.02 v1(9374.02,1492.13)
MEM.BUS_A16: U5.AF21 U24.D7 U25.21 U26.21 U27.27 U28.27 | length 4898.6
  Top Layer w5: U28.27@9405.51,1417.32 v1(9405.51,1468.5) ; U27.27@9405.51,2122.05 v1(9405.51,2173.23) ; U5.AF21@10283.46,2952.76 10283.46,2933.07 10296.68,2919.86 10296.68,2698.01 10326.77,2667.92 U25.21@10326.77,2570.87 v1(10326.77,2519.69) ; v1(10326.77,1814.96) U26.21@10326.77,1866.14 ; U24.D7@11437.01,2098.25 v1(11456.69,2117.93)
  MidLayer2 w5: v1(9405.51,1468.5) 9405.51,1716.54 9417.32,1728.35 9417.32,1799.21 9425.2,1807.09 9425.2,2011.81 9425.2,2051.18 9405.51,2070.87 v1(9405.51,2173.23) ; v1(10311.02,1543.31) 10326.77,1559.06 10326.77,2023.62 10307.09,2043.31 10307.09,2181.1 10314.96,2188.98 10314.96,2385.83 10326.77,2397.64 v1(10326.77,2519.69)
  MidLayer4 w5: v1(10326.77,1814.96) 10350.39,1838.58 10546.55,1838.58 10578.05,1807.09 11485.86,1807.09 11539.68,1860.91 11539.68,2074.9 11516.08,2098.5 11476.13,2098.5 v1(11456.69,2117.93)
  MidLayer3 w5: v1(9405.51,1468.5) 9405.51,1492.13 9484.25,1570.87 10283.46,1570.87 v1(10311.02,1543.31)
MEM.BUS_A17: U5.AC17 U24.E7 U27.42 U28.42 | length 3934.2
  Top Layer w5: U28.42@9877.95,1417.32 v1(9877.95,1492.13) ; U27.42@9877.95,2122.05 v1(9877.95,2196.85) ; U24.E7@11437.01,2058.88 v1(11456.69,2039.19)
  Top Layer w7.87: U5.AC17@10125.98,3070.87 v1(10145.67,3051.18)
  MidLayer1 w5: v1(9877.95,2196.85) 9877.95,2460.72 9942.68,2525.45 9996.76,2525.45 10147.48,2676.18 10147.48,2851.52 10113,2886 10113,2912.21 10125.99,2925.2 10125.99,3031.5 v1(10145.67,3051.18)
  MidLayer2 w5: v1(9877.95,1492.13) 9877.95,1716.54 9897.64,1736.22 9897.64,1799.21 9889.76,1807.09 9889.76,2019.68 9877.95,2031.5 v1(9877.95,2196.85)
  MidLayer3 w5: v1(9877.95,1492.13) 9905.51,1519.69 10084.28,1519.69 10166.96,1437.01 10724.59,1437.01 11161.42,1873.84 11448.82,1873.84 11476.38,1901.4 11476.38,2019.51 v1(11456.69,2039.19)
MEM.BUS_A18: U5.AD17 U24.B3 U27.43 U28.43 | length 3323.1
  Top Layer w5: U28.43@9909.45,1417.32 v1(9909.45,1468.5) ; U27.43@9909.45,2122.05 v1(9909.45,2173.23) ; v1(11259.84,2196.67) U24.B3@11279.53,2176.99
  Top Layer w7.87: U5.AD17@10125.98,3031.5 v1(10145.67,3011.81)
  MidLayer1 w5: v1(9909.45,2173.23) 9909.45,2424 10144.71,2659.27 10157.48,2672.03 10157.48,2905.51 10145.67,2917.32 v1(10145.67,3011.81)
  MidLayer2 w5: v1(9909.45,1468.5) 9909.45,1716.54 9921.26,1728.35 9921.26,1799.21 9929.13,1807.09 9929.13,2027.56 9909.45,2047.24 v1(9909.45,2173.23)
  MidLayer4 w5: v1(9909.45,2173.23) 9909.45,2220.47 9996.06,2307.09 10948.82,2307.09 11078.92,2176.99 11228.35,2176.99 11240.16,2188.8 11240.16,2192.74 11244.09,2196.67 v1(11259.84,2196.67)
MEM.BUS_A19: U5.AC18 U24.C4 U27.44 U28.44 | length 4264.8
  Top Layer w5: U28.44@9940.94,1417.32 v1(9940.94,1492.13) ; U27.44@9940.94,2122.05 v1(9940.94,2196.85) ; v1(11299.21,2157.3) U24.C4@11318.9,2137.62
  Top Layer w7.87: U5.AC18@10165.35,3070.87 v1(10185.04,3051.18)
  MidLayer1 w5: v1(9940.94,2196.85) 9940.94,2379 10204.72,2642.78 10204.72,2874.02 10204.72,2889.76 10204.72,3031.5 v1(10185.04,3051.18)
  MidLayer2 w5: v1(9940.94,1492.13) 9940.94,1716.54 9960.63,1736.22 9960.63,2177.17 v1(9940.94,2196.85)
  MidLayer3 w5: v1(9940.94,1492.13) 9958.5,1509.69 10080.14,1509.69 10164.63,1425.2 10733.38,1425.2 11169.29,1861.11 11169.29,1862.03 11460.63,1862.03 11496.06,1897.46 11496.06,1980.14 11527.56,2011.63 11527.56,2196.67 11507.87,2216.36 11358.27,2216.36 v1(11299.21,2157.3)
MEM.BUS_A20: U5.W23 U24.D5 U27.28 U28.28 | length 5003.1
  Top Layer w5: U28.28@9437.01,1417.32 v1(9437.01,1492.13) ; U27.28@9437.01,2122.05 v1(9437.01,2196.85) ; U24.D5@11358.27,2098.25 v1(11377.95,2117.93)
  Top Layer w7.87: U5.W23@10362.2,3228.35 v1(10381.89,3208.66)
  MidLayer1 w5: v1(10381.89,3208.66) 10401.58,3188.98 10543.31,3188.98 10562.99,3188.98 10622.05,3188.98 10740.16,3070.87 10740.16,2912.69 11346.46,2306.39 11346.46,2149.43 v1(11377.95,2117.93)
  MidLayer2 w5: v1(9437.01,1492.13) 9437.01,1716.54 9456.69,1736.22 9456.69,1751.97 9456.69,1799.21 9448.82,1807.09 9448.82,2059.05 ; v1(9437.01,2196.85) 9437.01,2070.87 9448.82,2059.06
  MidLayer3 w5: v1(9437.01,1492.13) 9503.94,1559.06 10220.47,1559.06 10255.91,1523.62 10318.9,1523.62 10338.58,1543.31 10482,1543.31 10557.31,1468 10716.21,1468 11145.67,1897.46 11389.76,1897.46 11397.64,1905.34 11397.64,2058.88 11377.95,2078.56 v1(11377.95,2117.93)
MEM.BUS_A21: U5.AA24 U24.D4 | length 1581.4
  Top Layer w5: v1(11299.21,2117.93) U24.D4@11318.9,2098.25
  Top Layer w7.87: U5.AA24@10401.58,3149.61 v1(10421.26,3129.92)
  MidLayer1 w5: v1(10421.26,3129.92) 10543.31,3129.92 10562.99,3129.92 10649.61,3129.92 10716.54,3062.99 10716.54,2908.02 11318.9,2305.66 11318.9,2137.62 v1(11299.21,2117.93)
MEM.BUS_A22: U5.W24 U24.C5 | length 1618.6
  Top Layer w5: U24.C5@11358.27,2137.62 v1(11377.95,2157.3)
  Top Layer w7.87: U5.W24@10401.58,3228.35 v1(10421.26,3208.66)
  MidLayer1 w5: v1(10421.26,3208.66) 10543.31,3208.66 10562.99,3208.66 10618.11,3208.66 10751.97,3074.8 10751.97,2915.02 11358.27,2308.72 11358.27,2176.99 v1(11377.95,2157.3)
MEM.BUS_A23: U5.U24 U24.B8 | length 1706.3
  Top Layer w5: U24.B8@11476.38,2176.99 v1(11496.06,2196.67)
  Top Layer w7.87: U5.U24@10401.58,3307.09 v1(10421.26,3287.4)
  MidLayer1 w5: v1(10421.26,3287.4) 10515.99,3287.4 10539.62,3263.78 10610.24,3263.78 10787.4,3086.61 10787.4,2922.01 11428.83,2280.59 11459.33,2280.59 11496.06,2243.86 v1(11496.06,2196.67)
MEM.BUS_A24: U5.V24 U24.C8 | length 1720.2
  Top Layer w5: U24.C8@11476.38,2137.62 v1(11496.06,2157.3)
  Top Layer w7.87: U5.V24@10401.58,3267.72 v1(10421.26,3248.03)
  MidLayer1 w5: v1(10421.26,3248.03) 10482.68,3248.03 10489.26,3241.45 10616.81,3241.45 10775.59,3082.68 10775.59,2919.68 11424.69,2270.59 11455.19,2270.59 11476.38,2249.4 11476.38,2176.99 v1(11496.06,2157.3)
MEM.BUS_D0: U5.AB26 U24.E3 U25.2 U27.7 | length 2983.8
  Top Layer w5: v1(9751.97,2496.06) U27.7@9751.97,2570.87 ; U5.AB26@10480.32,3110.24 10500,3110.24 10507.87,3102.36 10543.31,3102.36 10562.99,3102.36 10673.77,3102.36 10925.2,2850.94 U25.2@10925.2,2570.87 v1(10925.2,2496.06) ; v1(11259.84,2039.19) U24.E3@11279.53,2058.88
  MidLayer3 w5: v1(9751.97,2496.06) 9771.65,2476.38 10503.94,2476.38 10535.43,2507.87 10535.43,2551.18 10559.06,2574.8 10685.04,2574.8 10759.84,2500 10838.58,2500 10854.33,2515.75 10905.51,2515.75 v1(10925.2,2496.06) 11015.75,2496.06 11133.86,2377.95 11133.86,2110.06 11185.04,2058.88 11240.16,2058.88 v1(11259.84,2039.19)
MEM.BUS_D1: U5.AB25 U24.H3 U25.4 U27.8 | length 3127.2
  Top Layer w5: v1(9720.47,2519.69) U27.8@9720.47,2570.87 ; U5.AB25@10440.95,3110.24 10460.63,3090.55 10543.31,3090.55 10562.99,3090.55 10660.58,3090.55 10862.21,2888.93 U25.4@10862.21,2570.87 v1(10862.21,2496.06) ; v1(11259.84,1921.08) U24.H3@11279.53,1940.77
  MidLayer3 w5: v1(9720.47,2519.69) 9720.47,2500 9755.9,2464.57 10511.81,2464.57 10547.24,2500 10547.24,2547.24 10562.99,2562.99 10677.17,2562.99 10716.54,2523.62 10716.54,2488.19 10728.35,2476.38 10842.52,2476.38 v1(10862.21,2496.06) 10881.89,2476.38 11015.75,2476.38 11122.05,2370.08 11122.05,2106.12 11200.79,2027.38 11200.79,1989.98 11210.63,1980.14 11236.22,1980.14 11240.16,1976.2 11240.16,1940.77 v1(11259.84,1921.08)
MEM.BUS_D2: U5.AC26 U24.E4 U25.5 U27.9 | length 3803.1
  Top Layer w5: v1(9688.98,2496.06) U27.9@9688.98,2570.87 ; U5.AC26@10480.32,3070.87 10500,3070.87 10523.62,3047.24 10543.31,3047.24 10562.99,3047.24 10678.78,3047.24 10830.71,2895.31 U25.5@10830.71,2570.87 v1(10830.71,2519.69) 10830.71,2496.06 v1(10862.2,2464.57) ; v1(11299.21,2039.19) U24.E4@11318.9,2058.88
  MidLayer3 w5: v1(9688.98,2496.06) 9590.55,2496.06 9531.5,2555.12 9385.83,2555.12 9374.02,2543.31 9374.02,2523.62 9354.33,2503.94 9354.33,2484.25 9366.14,2472.44 9405.51,2472.44 9488.19,2389.76 9830.71,2389.76 9858.27,2417.32 10814.96,2417.32 v1(10862.2,2464.57) ; v1(10830.71,2519.69) 10854.33,2543.31 10988.19,2543.31 11145.67,2385.83 11145.67,2117.93 11192.91,2070.69 11267.72,2070.69 v1(11299.21,2039.19)
MEM.BUS_D3: U5.AC25 U24.H4 U25.7 U27.10 | length 3235
  Top Layer w5: v1(9657.48,2519.69) U27.10@9657.48,2570.87 ; U5.AC25@10440.95,3070.87 10460.63,3051.18 10500,3051.18 10515.75,3035.43 10547.24,3035.43 10562.99,3035.43 10673.23,3035.43 10685.04,3023.62 10767.72,2940.95 U25.7@10767.72,2570.87 v1(10767.72,2519.69) ; v1(11299.21,1921.08) U24.H4@11318.9,1940.77
  MidLayer3 w5: v1(9657.48,2519.69) 9657.48,2551.18 9673.23,2566.93 10480.32,2566.93 10500,2586.61 10700.79,2586.61 v1(10767.72,2519.69) 10803.15,2555.12 10996.06,2555.12 11168.31,2382.87 11213.53,2382.87 11227.9,2368.5 11227.9,2322 11176.68,2270.78 11176.68,2124.95 11206.68,2094.95 11316.29,2094.95 11340.55,2070.69 11340.55,1962.42 v1(11299.21,1921.08)
MEM.BUS_D4: U5.AD25 U24.H5 U25.8 U27.13 | length 3127.2
  Top Layer w5: U27.13@9562.99,2570.87 v1(9562.99,2496.06) 9590.55,2468.5 9811.02,2468.5 9814.96,2464.57 10704.72,2464.57 v1(10736.22,2496.06) U25.8@10736.22,2570.87 10736.22,2828.78 10635,2930 10635,2989 10612.19,3011.81 10460.63,3011.81 U5.AD25@10440.95,3031.5 ; U24.H5@11358.27,1940.77 v1(11377.95,1921.08)
  MidLayer2 w5: v1(10736.22,2496.06) 11094.67,2137.62 11385.83,2137.62 11397.64,2125.81 11397.64,2110.06 11437.01,2070.69 11437.01,1948.64 11429.13,1940.77 11397.64,1940.77 v1(11377.95,1921.08)
MEM.BUS_D5: U5.AA22 U24.E5 U25.10 U27.14 | length 3626.7
  Top Layer w5: v1(9531.5,2519.69) U27.14@9531.5,2570.87 ; v1(10673.23,2496.06) U25.10@10673.23,2570.87 v1(10673.23,2622.05) ; U24.E5@11358.27,2058.88 v1(11377.95,2039.19)
  Top Layer w7.87: U5.AA22@10322.83,3149.61 v1(10342.52,3129.92)
  MidLayer2 w5: v1(10342.52,3129.92) 10362.21,3110.24 10543.31,3110.24 10566.93,3110.24 10653.54,3110.24 10690.79,3072.99 10690.79,2777.56 10673.23,2760 v1(10673.23,2622.05) ; v1(10673.23,2496.06) 10673.23,2299.21 10834.65,2137.8 11012.54,2137.8 11075.71,2074.63 11342.52,2074.63 v1(11377.95,2039.19)
  MidLayer3 w5: v1(9531.5,2519.69) 9507.87,2543.31 9393.7,2543.31 9385.83,2535.43 9385.83,2511.81 9496.06,2401.58 9822.83,2401.58 9850.39,2429.13 10606.3,2429.13 v1(10673.23,2496.06)
MEM.BUS_D6: U5.AB22 U24.H6 U25.11 U27.15 | length 3633.3
  Top Layer w5: v1(9500,2496.06) U27.15@9500,2570.87 ; v1(10641.73,2519.69) U25.11@10641.73,2570.87 v1(10641.73,2622.05) ; U24.H6@11397.64,1940.77 v1(11417.32,1921.08)
  Top Layer w7.87: U5.AB22@10322.83,3110.24 v1(10342.52,3090.55)
  MidLayer2 w5: v1(10342.52,3090.55) 10362.2,3070.87 10662.17,3070.87 10680.79,3052.24 10680.79,2781.7 10641.73,2742.65 v1(10641.73,2622.05) ; v1(10641.73,2519.69) 10618.11,2496.06 10618.11,2129.92 10696.85,2051.18 10911.42,2051.18 11109.4,1853.2 11349.44,1853.2 v1(11417.32,1921.08)
  MidLayer3 w5: v1(9500,2496.06) 9570.87,2425.2 9807.09,2425.2 9834.65,2452.76 10519.69,2452.76 10559.06,2492.13 10559.06,2535.43 10570.87,2547.24 10614.17,2547.24 v1(10641.73,2519.69)
MEM.BUS_D7: U5.AE24 U24.E6 U25.13 U27.16 | length 2938.5
  Top Layer w5: v1(9468.5,2519.69) U27.16@9468.5,2570.87 ; U5.AE24@10401.58,2992.13 10421.26,2972.44 10421.26,2937.01 10444.88,2913.39 10444.88,2889.76 10444.88,2870.08 10444.88,2759.84 10578.74,2625.99 U25.13@10578.74,2570.87 v1(10578.74,2519.69) ; U24.E6@11397.64,2058.88 v1(11417.32,2039.19)
  MidLayer2 w5: v1(10578.74,2519.69) 10598.42,2539.37 10661.42,2539.37 10696.85,2503.94 10696.85,2481.77 11080.37,2098.25 11389.76,2098.25 11417.32,2070.69 v1(11417.32,2039.19)
  MidLayer3 w5: v1(9468.5,2519.69) 9468.5,2496.06 9551.18,2413.39 9814.96,2413.39 9842.52,2440.95 10527.56,2440.95 10578.74,2492.13 v1(10578.74,2519.69)
MEM.BUS_D8: U5.AC22 U24.F3 U25.42 U27.29 | length 3385
  Top Layer w5: U27.29@9468.5,2122.05 v1(9468.5,2173.23) 9468.5,2196.85 9570.87,2299.21 9988.19,2299.21 10055.12,2232.28 10055.12,2072.02 10088.68,2038.45 10546.33,2038.45 10578.74,2070.87 U25.42@10578.74,2122.05 v1(10578.74,2173.23) ; v1(11259.84,1999.82) U24.F3@11279.53,2019.51
  Top Layer w7.87: U5.AC22@10322.83,3070.87 v1(10342.52,3051.18)
  MidLayer1 w5: v1(10342.52,3051.18) 10362.2,3031.5 10362.2,2996.06 10381.89,2976.38 10381.89,2889.76 10381.89,2870.08 10381.89,2821.24 10515.75,2687.39 10515.75,2555.12 10578.74,2492.13 v1(10578.74,2173.23)
  MidLayer4 w5: v1(10578.74,2173.23) 10625.98,2220.47 10811.02,2220.47 10871.04,2160.45 10939.4,2160.45 11057.04,2042.82 11099.47,2042.82 11162.14,1980.14 11240.16,1980.14 v1(11259.84,1999.82)
MEM.BUS_D9: U5.AD23 U24.G3 U25.44 U27.30 | length 3301
  Top Layer w5: U27.30@9500,2122.05 v1(9500,2196.85) 9590.55,2287.4 9984.25,2287.4 10043.31,2228.35 10043.31,2066.93 10082.68,2027.56 10598.42,2027.56 10641.73,2070.87 U25.44@10641.73,2122.05 v1(10641.73,2173.23) ; v1(11259.84,1960.45) U24.G3@11279.53,1980.14
  Top Layer w7.87: U5.AD23@10362.2,3031.5 v1(10381.89,3011.81)
  MidLayer1 w5: v1(10381.89,3011.81) 10397.64,2996.06 10397.64,2825.11 10566.93,2655.82 10566.93,2562.99 10641.73,2488.19 v1(10641.73,2173.23)
  MidLayer4 w5: v1(10641.73,2173.23) 10675.16,2139.8 10931.77,2139.8 11050.37,2021.2 11092.8,2021.2 11173.23,1940.77 11240.16,1940.77 v1(11259.84,1960.45)
MEM.BUS_D10: U5.AD10 U24.F4 U25.45 U27.31 | length 3532
  Top Layer w5: U27.31@9531.5,2122.05 v1(9531.5,2173.23) 9531.5,2196.85 9610.24,2275.59 9980.32,2275.59 10031.5,2224.41 10031.5,2062.99 10078.74,2015.75 10618.11,2015.75 10673.23,2070.87 U25.45@10673.23,2122.05 v1(10673.23,2196.85) ; v1(11299.21,1999.82) U24.F4@11318.9,2019.51
  Top Layer w7.87: v1(9830.71,3011.81) U5.AD10@9850.39,3031.5
  MidLayer1 w5: v1(9531.5,2173.23) 9531.5,2492.13 9625.98,2586.61 9665.35,2586.61 9818.9,2740.16 9818.9,2870.08 9818.9,2889.76 9818.9,2905.51 9830.71,2917.32 v1(9830.71,3011.81)
  MidLayer2 w5: v1(10673.23,2196.85) 10771.65,2098.43 10996.06,2098.43 11210.59,1883.9 11303.9,1883.9 11318.9,1898.9 11318.9,1980.14 v1(11299.21,1999.82)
